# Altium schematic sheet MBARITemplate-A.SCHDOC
size A; Organization: Monterey Bay Aquarium Research Institute; Address1: 7700 Sandholdt Rd; Address2: Moss Landing, CA 95039-9644; CompanyName: MBARI
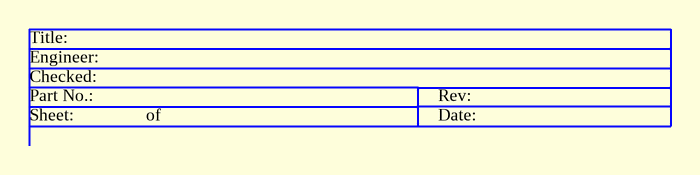
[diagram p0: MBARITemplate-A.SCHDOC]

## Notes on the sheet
- Sheet:
- Title:
- Engineer:
- Part No.:
- Checked:
- of
- Rev:
- Date:
